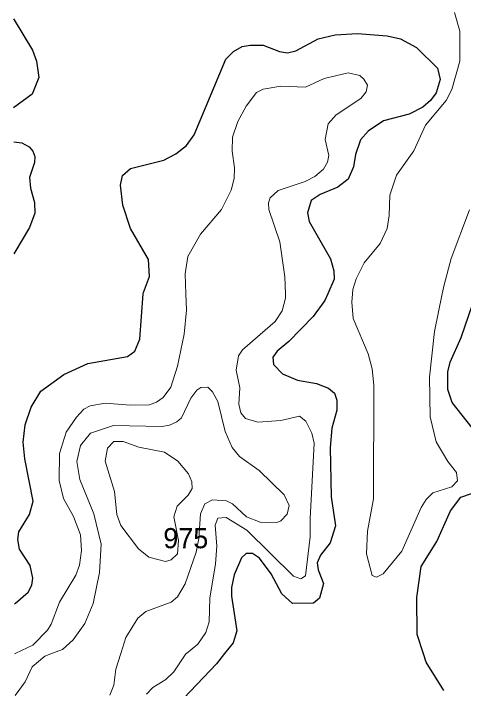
# Model space of a CAD drawing. Extents: x 473.9 to 500, y 7733.1 to 7760.8.
# Drawn here: x 473.911 to 475.698, y 7743.401 to 7746.08 of the extents above; entities that cross this region are included whole.
import ezdxf

# ---------------------------------------------------------------- set-up
doc = ezdxf.new("R2010")
doc.units = 0
doc.header["$LTSCALE"] = 0.032
doc.layers.add('1', color=7, linetype='Continuous', lineweight=25)
doc.layers.add('2', color=7, linetype='Continuous', lineweight=13)
doc.layers.add('21', color=7, linetype='Continuous')

msp = doc.modelspace()

# ---------------------------------------------------------------- linework, layer by layer
at = {"layer": '1'}
for points in [[(473.9114, 7746.059), (473.9142, 7746.0545), (473.9872, 7745.9343), (474.0033, 7745.8909), (474.0123, 7745.8256), (473.9849, 7745.7593), (473.912, 7745.7049)], [(473.915, 7743.7357), (473.9199, 7743.74), (473.9695, 7743.7837), (473.9841, 7743.8114), (473.9879, 7743.8394), (473.9773, 7743.8893), (473.9359, 7743.9548), (473.9285, 7743.9931), (473.9327, 7744.0225), (473.9744, 7744.0915), (473.9889, 7744.1452), (473.9564, 7744.3124), (473.9504, 7744.3788), (473.9574, 7744.4479), (473.9814, 7744.5171), (474.0199, 7744.5808), (474.1114, 7744.6468), (474.2062, 7744.6903), (474.3638, 7744.719), (474.3928, 7744.7394), (474.4132, 7744.7872), (474.4267, 7744.9675), (474.4271, 7744.9725), (474.4509, 7745.0359), (474.4473, 7745.1041), (474.3754, 7745.2272), (474.3452, 7745.319), (474.3363, 7745.3983), (474.344, 7745.4369), (474.3761, 7745.4644), (474.5079, 7745.4979), (474.5553, 7745.5225), (474.5977, 7745.556), (474.6293, 7745.5979), (474.754, 7745.8986), (474.7854, 7745.9294), (474.8199, 7745.9488), (474.8514, 7745.9545), (474.903, 7745.9536), (474.968, 7745.9286), (474.9995, 7745.9239), (475.0317, 7745.9312), (475.1214, 7745.979), (475.188, 7745.9952), (475.2777, 7746.0002), (475.3948, 7745.9904), (475.4472, 7745.9791), (475.5114, 7745.9451), (475.5949, 7745.8622), (475.605, 7745.8179), (475.5898, 7745.7644), (475.5675, 7745.7345), (475.5368, 7745.708), (475.4822, 7745.6798), (475.3807, 7745.6537), (475.3191, 7745.6131), (475.2892, 7745.5789), (475.2698, 7745.52), (475.2616, 7745.4712), (475.2395, 7745.4217), (475.1995, 7745.3904), (475.1288, 7745.3621), (475.0931, 7745.3381), (475.0786, 7745.2881), (475.0847, 7745.2548), (475.1706, 7745.1068), (475.1835, 7745.0586), (475.1844, 7745.0258), (475.1591, 7744.9675), (475.1477, 7744.9411), (475.1017, 7744.8773), (475.0048, 7744.7786), (474.9576, 7744.7402), (474.9409, 7744.7161), (474.9439, 7744.6871), (474.9794, 7744.6505), (475.0385, 7744.6251), (475.115, 7744.6114), (475.1615, 7744.5933), (475.1854, 7744.5732), (475.1951, 7744.5452), (475.1957, 7744.5062), (475.1751, 7744.4337), (475.1683, 7744.3572), (475.1725, 7744.1614), (475.1892, 7744.0465), (475.1683, 7743.979), (475.13, 7743.9303), (475.1173, 7743.8998), (475.1216, 7743.872), (475.1426, 7743.8175), (475.1261, 7743.7596), (475.1023, 7743.7399), (475.0186, 7743.7386), (474.9763, 7743.7764), (474.9344, 7743.8567), (474.8882, 7743.9182), (474.8607, 7743.9368), (474.8347, 7743.9373), (474.8163, 7743.9194)], [(473.9122, 7745.5699), (473.9132, 7745.5698), (473.9445, 7745.5661), (473.9734, 7745.551), (473.9879, 7745.5339), (473.9962, 7745.5123), (473.9949, 7745.489), (473.9752, 7745.4287), (473.979, 7745.3864), (473.9947, 7745.3301), (473.9959, 7745.2874), (473.9754, 7745.2306), (473.9166, 7745.1328), (473.9129, 7745.1266)], [(475.7328, 7744.4356), (475.6536, 7744.5364), (475.6355, 7744.5875), (475.6356, 7744.6575), (475.6454, 7744.696), (475.6882, 7744.7939), (475.7485, 7744.9675)], [(475.6199, 7743.3941), (475.5496, 7743.5058), (475.5388, 7743.539), (475.5139, 7743.6157), (475.5124, 7743.7629), (475.5303, 7743.885), (475.5916, 7743.9844), (475.6463, 7744.1066), (475.6871, 7744.1609), (475.7301, 7744.1746)], [(474.8163, 7743.9194), (474.7871, 7743.8529), (474.7773, 7743.8021), (474.7771, 7743.7678), (474.7984, 7743.6303), (474.7833, 7743.5822), (474.7497, 7743.5402), (474.7172, 7743.4995), (474.5874, 7743.3633)]]:
    msp.add_lwpolyline(points, dxfattribs=at)
at = {"layer": '2'}
for points in [[(475.662, 7746.0839), (475.6829, 7746.0099), (475.6836, 7745.8904), (475.6521, 7745.7777), (475.6293, 7745.7347), (475.5468, 7745.6364), (475.5009, 7745.5348), (475.4316, 7745.4379), (475.4053, 7745.3588), (475.4031, 7745.2782), (475.395, 7745.2269), (475.3669, 7745.1666), (475.3038, 7745.0906), (475.2716, 7745.0263), (475.2586, 7744.9844), (475.2575, 7744.9675), (475.2553, 7744.9342), (475.2602, 7744.8694), (475.32, 7744.7293), (475.3358, 7744.6695), (475.342, 7744.6045), (475.3405, 7744.1533), (475.3167, 7744.0258), (475.3135, 7743.9353), (475.335, 7743.8495), (475.3526, 7743.8432), (475.3789, 7743.8565), (475.4533, 7743.9459), (475.5305, 7744.1195), (475.5504, 7744.1518), (475.5766, 7744.1774), (475.6521, 7744.2019), (475.6745, 7744.2247), (475.6698, 7744.2578), (475.6358, 7744.3018), (475.5896, 7744.3798), (475.5651, 7744.4789), (475.5624, 7744.637), (475.5833, 7744.8183), (475.6135, 7744.9675), (475.6206, 7745.0027), (475.6484, 7745.1069), (475.7212, 7745.3001)], [(474.4401, 7743.379), (474.4643, 7743.4059), (474.5158, 7743.4377), (474.5481, 7743.468), (474.596, 7743.5384), (474.5984, 7743.5404), (474.6431, 7743.5777), (474.6744, 7743.6231), (474.6878, 7743.6654), (474.6907, 7743.7593), (474.714, 7743.8964), (474.719, 7743.9661), (474.7126, 7744.0497), (474.7227, 7744.0768), (474.7553, 7744.0799), (474.8373, 7744.0292), (475.0224, 7743.8473), (475.0516, 7743.8368), (475.0701, 7743.8482), (475.0896, 7744.0026), (475.0889, 7744.0765), (475.1055, 7744.3751), (475.0954, 7744.4142), (475.072, 7744.4624), (475.0468, 7744.482), (474.9728, 7744.4653), (474.8817, 7744.4575), (474.8328, 7744.4733), (474.8142, 7744.4951), (474.8058, 7744.5289), (474.8098, 7744.5938), (474.796, 7744.6651), (474.8046, 7744.7212), (474.8203, 7744.7453), (474.9497, 7744.857), (474.9786, 7744.9002), (474.9916, 7744.9497), (474.9909, 7744.9675), (474.9884, 7745.0349), (474.9687, 7745.1731), (474.9255, 7745.3013), (474.9233, 7745.3285), (474.9308, 7745.348), (474.962, 7745.3769), (475.0692, 7745.4128), (475.1077, 7745.433), (475.1426, 7745.4625), (475.1587, 7745.49), (475.1634, 7745.5157), (475.1484, 7745.5795), (475.1611, 7745.6418), (475.1925, 7745.677), (475.2902, 7745.7425), (475.3116, 7745.7689), (475.3162, 7745.7948), (475.3025, 7745.8192), (475.2863, 7745.8335), (475.2407, 7745.8442), (475.1453, 7745.8213), (475.0709, 7745.7873), (474.9733, 7745.7912), (474.902, 7745.7793), (474.8763, 7745.766), (474.8354, 7745.7118), (474.8015, 7745.6507), (474.7807, 7745.5892), (474.7793, 7745.5339), (474.7888, 7745.4679), (474.7873, 7745.4252), (474.7758, 7745.379), (474.7371, 7745.3019), (474.6535, 7745.2039), (474.6031, 7745.1153), (474.5928, 7745.0467), (474.5954, 7744.9675), (474.5976, 7744.903), (474.5895, 7744.8071), (474.563, 7744.6806)], [(474.563, 7744.6806), (474.5365, 7744.5969), (474.5062, 7744.5566), (474.4796, 7744.5375), (474.4512, 7744.5266), (474.3762, 7744.525), (474.2754, 7744.533), (474.2153, 7744.5229), (474.1913, 7744.5091), (474.161, 7744.4774), (474.1205, 7744.419), (474.0943, 7744.3333), (474.0925, 7744.2262), (474.1102, 7744.1558), (474.1495, 7744.084), (474.177, 7744.0111), (474.1819, 7743.9495), (474.1738, 7743.8906), (474.1588, 7743.8508), (474.0935, 7743.7433), (474.0615, 7743.6566), (474.0469, 7743.6328), (473.9886, 7743.5728), (473.9204, 7743.5415), (473.9153, 7743.5391), (473.9204, 7743.5415)], [(474.2944, 7743.3743), (474.3104, 7743.414), (474.3183, 7743.4778), (474.3376, 7743.5408), (474.3569, 7743.6038), (474.4057, 7743.6805), (474.4367, 7743.7072), (474.5378, 7743.7435), (474.5621, 7743.7652), (474.5928, 7743.817), (474.6369, 7743.942), (474.6473, 7743.9966), (474.6539, 7744.0942), (474.6715, 7744.1341), (474.701, 7744.1503), (474.7567, 7744.1454), (474.7806, 7744.1341), (474.8364, 7744.0831), (474.8913, 7744.0619), (474.9566, 7744.06), (474.9725, 7744.0662), (474.9983, 7744.0927), (475.0059, 7744.1278), (474.9858, 7744.1703), (474.8864, 7744.2663), (474.8093, 7744.3222), (474.7802, 7744.3572), (474.7516, 7744.4214), (474.7223, 7744.5402), (474.702, 7744.5783), (474.6833, 7744.5969), (474.6548, 7744.5951), (474.639, 7744.5849), (474.616, 7744.5528), (474.578, 7744.4758), (474.5593, 7744.4591), (474.5313, 7744.446), (474.4999, 7744.4413), (474.3086, 7744.4445), (474.2172, 7744.4145), (474.1775, 7744.3652), (474.1627, 7744.3026), (474.1746, 7744.2311), (474.2303, 7744.0942), (474.2591, 7743.9736), (474.2526, 7743.8616), (474.2277, 7743.7393), (474.1949, 7743.6595), (474.1486, 7743.5942), (474.1056, 7743.5557), (474.0664, 7743.5412), (474.0359, 7743.53), (473.9852, 7743.4879), (473.9575, 7743.4277), (473.9182, 7743.3736)]]:
    msp.add_lwpolyline(points, dxfattribs=at)
msp.add_lwpolyline([(474.5623, 7743.9359), (474.5659, 7743.9881), (474.5478, 7744.0825), (474.561, 7744.1249), (474.605, 7744.1684), (474.6206, 7744.1945), (474.6192, 7744.2218), (474.6066, 7744.2534), (474.5645, 7744.3038), (474.5109, 7744.3386), (474.4095, 7744.3586), (474.3467, 7744.3813), (474.3097, 7744.381), (474.2847, 7744.3549), (474.276, 7744.3038), (474.3127, 7744.1827), (474.3214, 7744.0921), (474.3373, 7744.0475), (474.4073, 7743.9557), (474.4488, 7743.923), (474.5144, 7743.9059), (474.5376, 7743.9118)], close=True, dxfattribs=at)

# ---------------------------------------------------------------- texts
at = {"layer": '21'}
msp.add_text('975', height=0.08, dxfattribs=at).set_placement((474.5062, 7743.9579))

doc.saveas('drawing.dxf')
